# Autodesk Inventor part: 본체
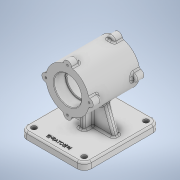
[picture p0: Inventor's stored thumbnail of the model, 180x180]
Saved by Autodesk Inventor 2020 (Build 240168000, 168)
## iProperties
Created: 2022-11
Part Number: 본체
Material: 일반
Document SubType Name: Modeling
Designer: owner
Density: 1 g/cm^3
Appearance: 기본값
Mass: 450.025 g
Surface Area: 797.07 cm^2
Volume: 450.025 cm^3
Author: owner
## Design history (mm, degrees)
sketch "스케치1"
  geometry: L1 (55, -65)-(-55, -65); L2 (-55, -65)-(-55, 65); L3 (-55, 65)-(55, 65); L4 (55, 65)-(55, -65); L5 (55, -65)-(-55, 65); L6 (-55, -65)-(55, 65); 1 further point
  constraints: 12 end point, 2 midpoint, 2 parallel, 1 horizontal, 1 perpendicular
  dimensions: "d0" = 110 distance of L2.end L3.end; "d1" = 130 distance of L1.end L2.end
extrude "돌출1" new body sketch "스케치1" distance "d2" = 12; taper "d3" = 0 deg
node "작업 평면2"
sketch "스케치3"
  geometry: L1 (0, 0)-(110, 0) reference; C1 r 37 at (55, 82); 2 further points
  constraints: 1 centre point, 1 midpoint, 1 vertical alignment
  dimensions: "d8" = 74 diameter of C1; "d9" = 82 distance from line of L1 C1.centre
extrude "돌출2" join sketch "스케치3" stored distance "d10" = 87; taper "d11" = 0 deg
sketch "스케치4"
  geometry: C1 r 37 at (0, 0) reference; C2 r 21 at (0, 0); 1 further point
  constraints: 1 centre point, 1 coincident
  dimensions: "d12" = 42 diameter of C2
extrude "돌출3" cut sketch "스케치4" extent not by distance; stored distance "d13" = 0; taper "d14" = 0 deg
sketch "스케치5"
  geometry: C1 r 21 at (0, 0) reference; C2 r 23.5 at (0, 0); 1 further point
  constraints: 1 centre point, 1 coincident
  dimensions: "d15" = 47 diameter of C2
extrude "돌출4" cut sketch "스케치5" distance "d16" = 19; taper "d17" = 0 deg
sketch "스케치6"
  geometry: A1 r 37 centre (0, 0) between (0, 37) and (-6.969, 36.338) reference; A2 r 7 centre (0, 37) between (6.969, 36.338) and (-6.969, 36.338); 1 further point
  constraints: 5 point on circle, 1 centre point, 1 vertical alignment
  dimensions: "d18" = 14 diameter of A2
extrude "돌출5" join sketch "스케치6" distance "d19" = 14; taper "d20" = 0 deg
fillet "모깎기1" dims "d21" = 3
sketch "스케치7"
  geometry: A1 r 7 centre (55, 119) between (61.969, 118.338) and (48.031, 118.338) reference; 4 further points
  constraints: 1 coincident
hole "구멍1" sketch "스케치7" at (55, 119) diameter "d22" = 3.242; stored, may be unused: countersink angle "d26" = 90 deg, drill point angle "d28" = 118 deg; dims "d23" = 8, "d24" = 4, "d25" = 2, "d27" = 10
fillet "모깎기3" dims "d33" = 3
sketch "스케치10"
  geometry: L1 (29.664, 55.036)-(14, 12); L2 (0, 12)-(110, 12) reference; L3 (0, 0)-(0, 12) reference; L4 (80.336, 55.036)-(96, 12); L5 (110, 0)-(110, 12) reference; A1 r 37 centre (55, 82) between (19.137, 72.896) and (45.896, 46.138) reference; A2 r 37 centre (55, 82) between (64.104, 46.138) and (90.862, 72.896) reference; A3 r 37 centre (55, 82) between (90.862, 91.104) and (64.104, 117.863) reference; A4 r 37 centre (55, 82) between (57.543, 118.913) and (52.457, 118.913) reference; A5 r 37 centre (55, 82) between (45.896, 117.863) and (19.137, 91.104) reference; A6 r 37 centre (55, 82) between (18.087, 84.543) and (18.087, 79.457) reference; A7 r 37 centre (55, 82) between (19.137, 72.896) and (45.896, 46.138) reference; A8 r 37 centre (55, 82) between (52.457, 45.087) and (57.543, 45.088) reference; A9 r 37 centre (55, 82) between (64.104, 46.138) and (90.862, 72.896) reference; A10 r 37 centre (55, 82) between (91.912, 79.457) and (91.912, 84.543) reference; A11 r 37 centre (55, 82) between (64.104, 46.138) and (90.862, 72.896) reference; A12 r 37 centre (55, 82) between (52.457, 45.088) and (57.543, 45.088) reference; A13 r 37 centre (55, 82) between (19.137, 72.896) and (45.896, 46.138) reference; A14 r 37 centre (55, 82) between (18.087, 84.543) and (18.087, 79.457) reference; A15 r 37 centre (55, 82) between (45.896, 117.863) and (19.137, 91.104) reference; A16 r 37 centre (55, 82) between (57.543, 118.913) and (52.457, 118.913) reference; A17 r 37 centre (55, 82) between (90.862, 91.104) and (64.104, 117.863) reference; A18 r 37 centre (55, 82) between (91.912, 79.457) and (91.912, 84.543) reference; 19 further points
  constraints: 4 end point, 2 point on circle, 2 point on line, 16 other
  dimensions: "d42" = 110 deg angle of L2 L1; "d43" = 14 distance from line of L3 L1.end; "d44" = 110 deg angle of L2 L4; "d45" = 14 distance from line of L5 L4.end
extrude "돌출7" join sketch "스케치10" stored distance "d46" = 10; taper "d47" = 0 deg
sketch "스케치13"
  geometry: L1 (12, -62)-(12, 62) reference; L2 (12, 15)-(31.944, 15); L3 (-25.2, -5)-(151.2, -5) reference; 1 further point
  constraints: 2 end point, 1 perpendicular, 1 point on line
  dimensions: "d58" = 20 distance between parallel lines of L3 L2
feature "리브1" sketch "스케치13" dims "d59" = 1, "d60" = 10, "d61" = 0, "d62" = 0, "d63" = 1, "d64" = 1
fillet "모깎기6" dims "d65" = 3
fillet "모깎기7" dims "d66" = 3
fillet "모깎기8" dims "d67" = 3
fillet "모깎기9" dims "d68" = 3
fillet "모깎기10" dims "d69" = 3
sketch "스케치14"
  geometry: 1 further point
sketch "스케치15"
  geometry: L1 (0, 91)-(0, -91) reference; L2 (77, 5)-(-77, 5) reference; 2 further points
  constraints: 1 vertical alignment, 1 other
  dimensions: "d70" = 58 distance from line of point (0, -53) L2
feature "엠보싱1" sketch "스케치15" dims "d0" = 110, "d1" = 130, "d13" = 0, "d71" = 0.5, "d72" = 0
fillet "모깎기11" dims "d73" = 12
fillet "모깎기12" dims "d74" = 3
sketch "스케치17"
  geometry: A1 r 9 centre (43, -53) between (43, -62) and (52, -53) reference; 2 further points
  constraints: 1 coincident
hole "구멍2" sketch "스케치17" at (43, -53) diameter "d76" = 9; stored, may be unused: countersink angle "d80" = 90 deg, drill point angle "d82" = 0 deg; dims "d77" = 8, "d78" = 4, "d79" = 2, "d81" = 10
chamfer "모따기1" distance "d83" = 1; stored, may be unused: second distance "d84" = 2, angle "d85" = 45 deg
fillet "모깎기13" dims "d86" = 1
node "솔리드1"
mirror "미러1"
pattern_circular "원형 패턴2" dims "d35" = 360 deg
mirror "미러3"
mirror "미러5"
mirror "미러6"
mirror "미러7"
node "투영된 루프2"
feature "A9D066F2-1C7D-4E18-AEED-F7BC21143FA4" dims "d76" = 9, "d77" = 8, "d78" = 4, "d79" = 2, "d80" = 90 deg, "d81" = 10, "d82" = 0
